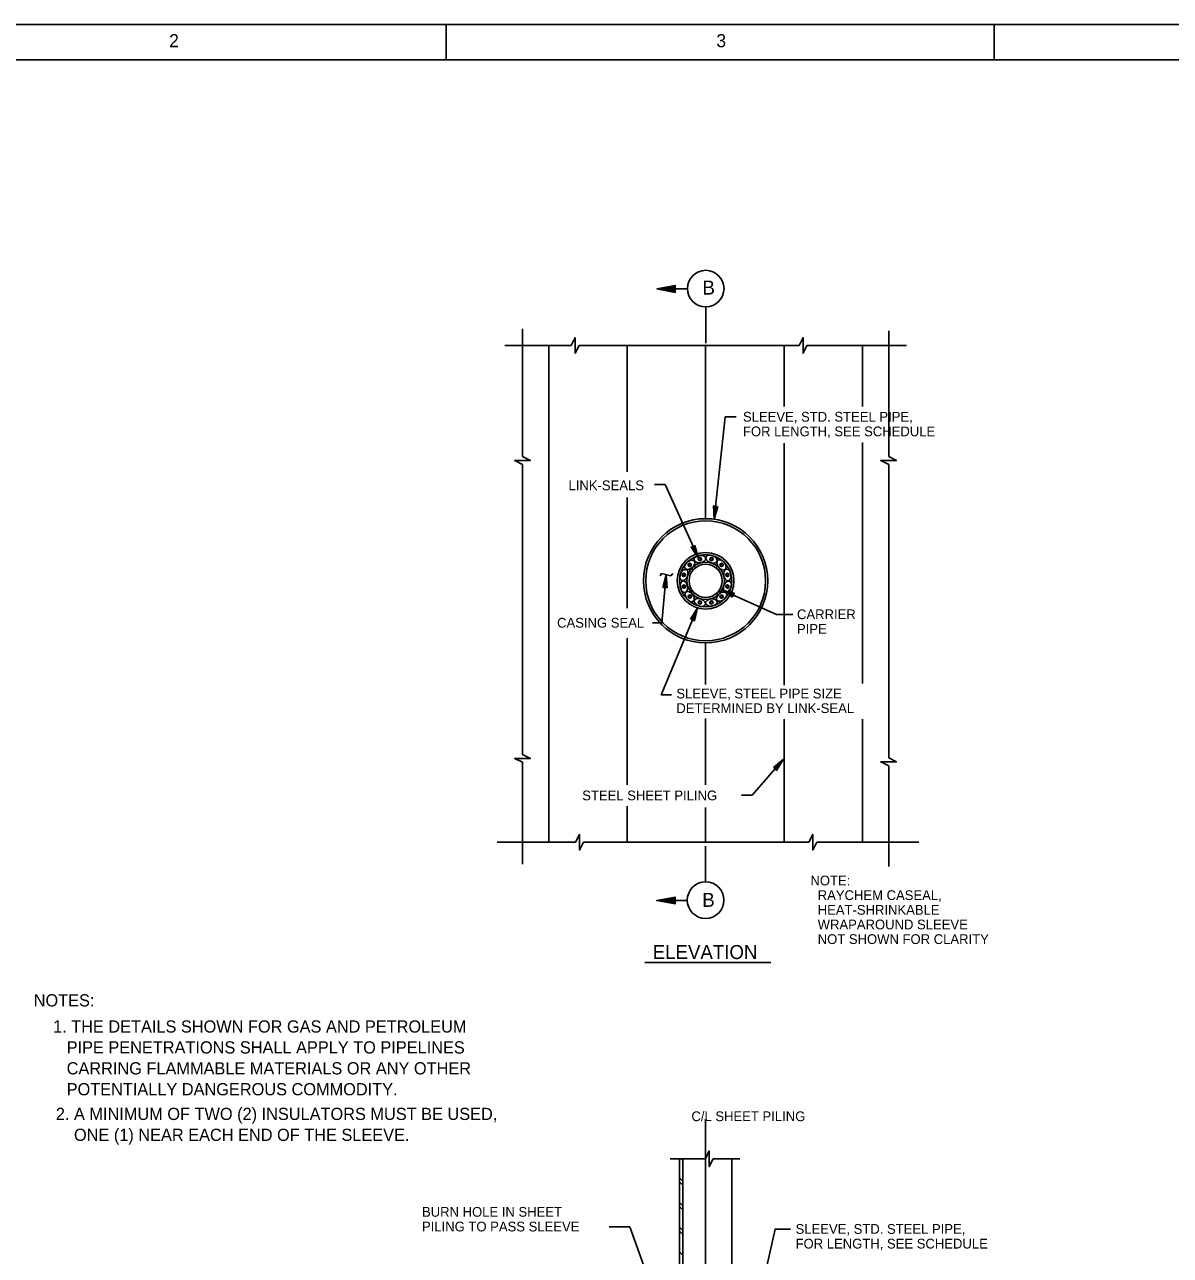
# Model space of a CAD drawing. Extents: x 22422.9 to 22498.9, y 22369.6 to 22415.
# Drawn here: x 22455.11 to 22477.02, y 22391.43 to 22414.97 of the extents above; entities that cross this region are included whole.
import ezdxf

# ---------------------------------------------------------------- set-up
doc = ezdxf.new("R2010")
doc.units = 0
for name, color, linetype in [('Level 1', 7, 'Continuous'), ('Level 10', 7, 'Continuous'), ('Level 2', 7, 'Continuous'), ('Level 3', 7, 'Continuous'), ('Level 4', 7, 'Continuous'), ('Level 7', 7, 'Continuous'), ('Level 8', 7, 'Continuous'), ('Level 9', 7, 'Continuous')]:
    doc.layers.add(name, color=color, linetype=linetype)

msp = doc.modelspace()

# ---------------------------------------------------------------- linework, layer by layer
at = {"layer": 'Level 1'}
for p, q in [((22464.63, 22406.705), (22464.63, 22409.15)), ((22471.63, 22406.705), (22471.63, 22409.109)), ((22464.287, 22408.828), (22465.56, 22408.828)), ((22465.709, 22408.828), (22469.918, 22408.828)), ((22470.067, 22408.828), (22471.973, 22408.828)), ((22464.63, 22401.005), (22464.63, 22406.555)), ((22471.63, 22400.939), (22471.63, 22406.555)), ((22468.216, 22405.596), (22468.216, 22405.596)), ((22468.222, 22405.665), (22468.222, 22405.665)), ((22467.85, 22404.894), (22467.85, 22404.894)), ((22467.864, 22404.826), (22467.864, 22404.826)), ((22467.89, 22404.536), (22467.86, 22404.566)), ((22467.935, 22404.579), (22467.905, 22404.609)), ((22468.327, 22404.577), (22468.357, 22404.607)), ((22468.372, 22404.534), (22468.402, 22404.563)), ((22467.288, 22404.469), (22467.259, 22404.424)), ((22467.288, 22404.469), (22467.466, 22404.424)), ((22467.367, 22404.356), (22467.367, 22404.356)), ((22467.373, 22404.425), (22467.373, 22404.425)), ((22467.466, 22404.424), (22467.502, 22404.469)), ((22467.846, 22404.108), (22467.876, 22404.138)), ((22467.888, 22404.062), (22467.918, 22404.092)), ((22468.367, 22404.059), (22468.338, 22404.088)), ((22468.411, 22404.104), (22468.381, 22404.134)), ((22468.536, 22404.261), (22468.536, 22404.261)), ((22468.603, 22404.243), (22468.603, 22404.243)), ((22467.97, 22403.814), (22467.97, 22403.814)), ((22467.989, 22403.88), (22467.989, 22403.88)), ((22464.63, 22398.906), (22464.63, 22400.856)), ((22469.574, 22400.865), (22469.574, 22400.865)), ((22469.62, 22400.917), (22469.62, 22400.917)), ((22471.63, 22398.863), (22471.63, 22400.789)), ((22464.141, 22399.328), (22465.643, 22399.328)), ((22465.792, 22399.328), (22470.105, 22399.328)), ((22470.254, 22399.328), (22472.207, 22399.328)), ((22468.13, 22384.598), (22468.13, 22394.033)), ((22467.453, 22393.274), (22468.126, 22393.274)), ((22468.275, 22393.274), (22468.785, 22393.274))]:
    msp.add_line(p, q, dxfattribs=at)
msp.add_lwpolyline([(22440.26, 22414.965), (22498.927, 22414.965), (22498.927, 22369.621), (22440.26, 22369.621)], close=True, dxfattribs=at)
for points in [[(22465.56, 22408.828), (22465.634, 22408.978), (22465.634, 22408.679), (22465.709, 22408.828)], [(22469.918, 22408.828), (22469.992, 22408.978), (22469.992, 22408.679), (22470.067, 22408.828)], [(22464.63, 22406.555), (22464.48, 22406.63), (22464.779, 22406.63), (22464.63, 22406.705)], [(22471.63, 22406.555), (22471.48, 22406.63), (22471.779, 22406.63), (22471.63, 22406.705)], [(22464.63, 22400.856), (22464.48, 22400.93), (22464.779, 22400.93), (22464.63, 22401.005)], [(22471.63, 22400.789), (22471.48, 22400.864), (22471.779, 22400.864), (22471.63, 22400.939)], [(22465.643, 22399.328), (22465.717, 22399.478), (22465.717, 22399.179), (22465.792, 22399.328)], [(22470.105, 22399.328), (22470.179, 22399.478), (22470.179, 22399.179), (22470.254, 22399.328)], [(22467.692, 22393.242), (22467.661, 22393.274)], [(22468.126, 22393.274), (22468.2, 22393.424), (22468.2, 22393.124), (22468.275, 22393.274)]]:
    msp.add_lwpolyline(points, dxfattribs=at)
for centre, radius in [((22468.13, 22404.328), 1.188), ((22468.13, 22404.328), 1.146), ((22468.13, 22404.328), 0.542), ((22468.13, 22404.328), 0.5), ((22468.019, 22404.743), 0.0313), ((22468.241, 22404.743), 0.0313), ((22467.826, 22404.632), 0.0313), ((22468.434, 22404.632), 0.0313), ((22467.715, 22404.44), 0.0313), ((22468.545, 22404.44), 0.0313), ((22467.715, 22404.217), 0.0313), ((22467.826, 22404.025), 0.0313), ((22468.434, 22404.025), 0.0313), ((22468.545, 22404.217), 0.0313), ((22468.019, 22403.913), 0.0313), ((22468.241, 22403.913), 0.0313)]:
    msp.add_circle(centre, radius, dxfattribs=at)
for centre, major_axis in [((22468.019, 22404.743), (0.111, 0.015)), ((22468.241, 22404.743), (0.104, -0.043)), ((22468.434, 22404.632), (0.0683, -0.089)), ((22467.715, 22404.44), (0.043, 0.104)), ((22467.826, 22404.632), (0.089, 0.0683)), ((22468.545, 22404.44), (0.015, -0.111)), ((22467.715, 22404.217), (-0.015, 0.111)), ((22468.545, 22404.217), (-0.043, -0.104)), ((22467.826, 22404.025), (-0.0683, 0.089)), ((22468.434, 22404.025), (-0.089, -0.0683)), ((22468.019, 22403.913), (-0.104, 0.043)), ((22468.241, 22403.913), (-0.111, -0.015))]:
    msp.add_ellipse(centre, major_axis=major_axis, ratio=0.623518, dxfattribs=at)
at = {"layer": 'Level 10'}
for p, q in [((22463.167, 22414.293), (22463.167, 22414.965)), ((22473.647, 22414.293), (22473.647, 22414.965)), ((22469.375, 22397.026), (22466.968, 22397.026))]:
    msp.add_line(p, q, dxfattribs=at)
at = {"layer": 'Level 2'}
for p, q in [((22465.13, 22399.328), (22465.13, 22408.828)), ((22466.63, 22406.414), (22466.63, 22408.828)), ((22468.13, 22405.516), (22468.13, 22408.828)), ((22469.63, 22407.662), (22469.63, 22408.828)), ((22471.13, 22407.662), (22471.13, 22408.828)), ((22469.63, 22402.33), (22469.63, 22406.96)), ((22471.13, 22402.363), (22471.13, 22406.971)), ((22466.63, 22403.804), (22466.63, 22405.919)), ((22467.292, 22403.524), (22467.375, 22404.447)), ((22467.977, 22403.809), (22467.282, 22402.145)), ((22467.111, 22403.524), (22467.292, 22403.524)), ((22466.63, 22400.423), (22466.63, 22403.233)), ((22468.13, 22402.347), (22468.13, 22403.141)), ((22467.282, 22402.145), (22467.476, 22402.145)), ((22468.13, 22400.423), (22468.13, 22401.694)), ((22469.63, 22399.328), (22469.63, 22401.681)), ((22471.13, 22399.328), (22471.13, 22401.681)), ((22469.02, 22400.23), (22469.62, 22400.917)), ((22468.817, 22400.23), (22469.02, 22400.23)), ((22466.63, 22399.328), (22466.63, 22400.015)), ((22468.13, 22399.328), (22468.13, 22399.99)), ((22467.63, 22389.342), (22467.63, 22393.274)), ((22467.692, 22389.342), (22467.692, 22393.274)), ((22468.63, 22389.342), (22468.63, 22393.274)), ((22466.283, 22391.97), (22466.68, 22391.97)), ((22467.63, 22389.342), (22466.68, 22391.97))]:
    msp.add_line(p, q, dxfattribs=at)
for points in [[(22468.714, 22407.463), (22468.504, 22407.463), (22468.293, 22405.507)], [(22467.151, 22406.168), (22467.353, 22406.168), (22467.991, 22404.758)], [(22468.361, 22405.751), (22468.293, 22405.507), (22468.279, 22405.76), (22468.349, 22405.752), (22468.301, 22405.576), (22468.291, 22405.748), (22468.336, 22405.743), (22468.308, 22405.643), (22468.303, 22405.736), (22468.322, 22405.734), (22468.315, 22405.712)], [(22467.926, 22405.003), (22467.991, 22404.758), (22467.851, 22404.969), (22467.915, 22404.998), (22467.962, 22404.822), (22467.867, 22404.964), (22467.908, 22404.983), (22467.935, 22404.882), (22467.884, 22404.96), (22467.901, 22404.968), (22467.906, 22404.946)], [(22467.311, 22404.202), (22467.375, 22404.447), (22467.394, 22404.195), (22467.323, 22404.201), (22467.368, 22404.378), (22467.381, 22404.207), (22467.336, 22404.211), (22467.363, 22404.312), (22467.369, 22404.219), (22467.35, 22404.22), (22467.356, 22404.243)], [(22469.796, 22403.681), (22469.483, 22403.681), (22468.432, 22404.154)], [(22468.642, 22404.014), (22468.432, 22404.154), (22468.676, 22404.089), (22468.647, 22404.025), (22468.495, 22404.126), (22468.661, 22404.082), (22468.642, 22404.04), (22468.556, 22404.098), (22468.646, 22404.074), (22468.638, 22404.057), (22468.619, 22404.07)], [(22467.843, 22403.595), (22467.977, 22403.809), (22467.919, 22403.563), (22467.854, 22403.59), (22467.95, 22403.745), (22467.911, 22403.578), (22467.869, 22403.595), (22467.925, 22403.683), (22467.903, 22403.593), (22467.885, 22403.6), (22467.898, 22403.619)], [(22469.425, 22400.756), (22469.62, 22400.917), (22469.487, 22400.702), (22469.434, 22400.748), (22469.574, 22400.865), (22469.484, 22400.719), (22469.45, 22400.749), (22469.53, 22400.814), (22469.481, 22400.736), (22469.467, 22400.748), (22469.485, 22400.762)], [(22469.755, 22391.93), (22469.458, 22391.93), (22468.882, 22389.353)]]:
    msp.add_lwpolyline(points, dxfattribs=at)
for radius in [0.359, 0.318]:
    msp.add_circle((22468.13, 22404.328), radius, dxfattribs=at)
at = {"layer": 'Level 3'}
for p, q in [((22467.548, 22409.909), (22467.781, 22409.909)), ((22468.131, 22408.871), (22468.131, 22409.56)), ((22468.129, 22399.251), (22468.129, 22398.563)), ((22467.546, 22398.213), (22467.779, 22398.213))]:
    msp.add_line(p, q, dxfattribs=at)
for points in [[(22467.548, 22409.958), (22467.548, 22409.976), (22467.198, 22409.909), (22467.548, 22409.844), (22467.548, 22409.958), (22467.287, 22409.91), (22467.531, 22409.864), (22467.531, 22409.939), (22467.375, 22409.91), (22467.515, 22409.884), (22467.515, 22409.919), (22467.465, 22409.91), (22467.498, 22409.904)], [(22467.546, 22398.262), (22467.546, 22398.28), (22467.196, 22398.213), (22467.546, 22398.148), (22467.546, 22398.262), (22467.285, 22398.215), (22467.529, 22398.168), (22467.529, 22398.243), (22467.373, 22398.215), (22467.513, 22398.188), (22467.513, 22398.223), (22467.463, 22398.215), (22467.496, 22398.208)]]:
    msp.add_lwpolyline(points, dxfattribs=at)
for centre in [(22468.131, 22409.916), (22468.129, 22398.22)]:
    msp.add_circle(centre, 0.35, dxfattribs=at)
at = {"layer": 'Level 8'}
for p, q in [((22468.293, 22405.507), (22468.293, 22405.507)), ((22468.301, 22405.576), (22468.301, 22405.576)), ((22467.962, 22404.822), (22467.962, 22404.822)), ((22467.991, 22404.758), (22467.991, 22404.758)), ((22468.012, 22404.769), (22467.992, 22404.75)), ((22467.999, 22404.724), (22467.992, 22404.75)), ((22468.012, 22404.769), (22468.038, 22404.762)), ((22468.045, 22404.736), (22468.038, 22404.762)), ((22468.215, 22404.737), (22468.222, 22404.762)), ((22468.248, 22404.769), (22468.222, 22404.762)), ((22468.248, 22404.769), (22468.267, 22404.75)), ((22468.26, 22404.724), (22468.267, 22404.75)), ((22467.807, 22404.651), (22467.8, 22404.625)), ((22467.819, 22404.606), (22467.8, 22404.625)), ((22467.807, 22404.651), (22467.833, 22404.658)), ((22467.845, 22404.613), (22467.819, 22404.606)), ((22467.852, 22404.639), (22467.833, 22404.658)), ((22467.845, 22404.613), (22467.852, 22404.639)), ((22468.026, 22404.717), (22467.999, 22404.724)), ((22468.026, 22404.717), (22468.045, 22404.736)), ((22468.234, 22404.717), (22468.215, 22404.737)), ((22468.234, 22404.717), (22468.26, 22404.724)), ((22468.408, 22404.639), (22468.427, 22404.658)), ((22468.415, 22404.613), (22468.408, 22404.639)), ((22468.415, 22404.613), (22468.441, 22404.606)), ((22468.453, 22404.651), (22468.427, 22404.658)), ((22468.441, 22404.606), (22468.46, 22404.625)), ((22468.453, 22404.651), (22468.46, 22404.625)), ((22467.368, 22404.378), (22467.368, 22404.378)), ((22467.375, 22404.447), (22467.375, 22404.447)), ((22467.689, 22404.447), (22467.708, 22404.466)), ((22467.689, 22404.447), (22467.696, 22404.42)), ((22467.722, 22404.413), (22467.696, 22404.42)), ((22467.734, 22404.459), (22467.708, 22404.466)), ((22467.741, 22404.433), (22467.722, 22404.413)), ((22467.741, 22404.433), (22467.734, 22404.459)), ((22468.519, 22404.433), (22468.526, 22404.459)), ((22468.519, 22404.433), (22468.538, 22404.414)), ((22468.526, 22404.459), (22468.552, 22404.466)), ((22468.538, 22404.414), (22468.564, 22404.421)), ((22468.571, 22404.447), (22468.552, 22404.466)), ((22468.571, 22404.447), (22468.564, 22404.421)), ((22467.689, 22404.21), (22467.696, 22404.236)), ((22467.689, 22404.21), (22467.708, 22404.191)), ((22467.722, 22404.243), (22467.696, 22404.236)), ((22467.734, 22404.198), (22467.708, 22404.191)), ((22467.741, 22404.224), (22467.722, 22404.243)), ((22467.741, 22404.224), (22467.734, 22404.198)), ((22467.819, 22404.051), (22467.8, 22404.032)), ((22467.845, 22404.044), (22467.819, 22404.051)), ((22467.845, 22404.044), (22467.852, 22404.017)), ((22468.415, 22404.044), (22468.408, 22404.018)), ((22468.415, 22404.044), (22468.441, 22404.051)), ((22468.432, 22404.154), (22468.432, 22404.154)), ((22468.441, 22404.051), (22468.46, 22404.032)), ((22468.495, 22404.126), (22468.495, 22404.126)), ((22468.519, 22404.224), (22468.538, 22404.243)), ((22468.519, 22404.224), (22468.526, 22404.198)), ((22468.526, 22404.198), (22468.552, 22404.191)), ((22468.538, 22404.243), (22468.564, 22404.236)), ((22468.571, 22404.21), (22468.552, 22404.191)), ((22468.571, 22404.21), (22468.564, 22404.236)), ((22467.807, 22404.005), (22467.8, 22404.032)), ((22467.807, 22404.005), (22467.833, 22403.998)), ((22467.852, 22404.017), (22467.833, 22403.998)), ((22467.977, 22403.809), (22467.977, 22403.809)), ((22468, 22403.932), (22467.993, 22403.906)), ((22468.012, 22403.887), (22467.993, 22403.906)), ((22468.026, 22403.939), (22468, 22403.932)), ((22468.012, 22403.887), (22468.038, 22403.894)), ((22468.026, 22403.939), (22468.045, 22403.92)), ((22468.045, 22403.92), (22468.038, 22403.894)), ((22468.234, 22403.939), (22468.215, 22403.92)), ((22468.215, 22403.92), (22468.222, 22403.894)), ((22468.248, 22403.887), (22468.222, 22403.894)), ((22468.234, 22403.939), (22468.26, 22403.932)), ((22468.248, 22403.887), (22468.267, 22403.906)), ((22468.26, 22403.932), (22468.267, 22403.906)), ((22468.408, 22404.018), (22468.427, 22403.999)), ((22468.453, 22404.006), (22468.427, 22403.999)), ((22468.453, 22404.006), (22468.46, 22404.032)), ((22467.95, 22403.745), (22467.95, 22403.745))]:
    msp.add_line(p, q, dxfattribs=at)
for points in [[(22467.692, 22392.846), (22467.63, 22392.909)], [(22467.692, 22392.771), (22467.63, 22392.833)], [(22467.692, 22392.375), (22467.63, 22392.437)], [(22467.692, 22392.3), (22467.63, 22392.362)], [(22467.692, 22391.904), (22467.63, 22391.966)], [(22467.692, 22391.828), (22467.63, 22391.891)], [(22467.692, 22391.432), (22467.63, 22391.495)]]:
    msp.add_lwpolyline(points, dxfattribs=at)
for centre in [(22468.019, 22404.743), (22468.241, 22404.743), (22467.826, 22404.632), (22468.434, 22404.632), (22467.715, 22404.44), (22468.545, 22404.44), (22467.715, 22404.217), (22467.826, 22404.025), (22468.434, 22404.025), (22468.545, 22404.217), (22468.019, 22403.913), (22468.241, 22403.913)]:
    msp.add_circle(centre, 0.0233, dxfattribs=at)
at = {"layer": 'Level 9'}
msp.add_line((22442.26, 22414.293), (22494.591, 22414.293), dxfattribs=at)

# ---------------------------------------------------------------- texts
at = {"layer": 'Level 1'}
for s, p in [('2', (22457.871, 22414.533)), ('3', (22468.335, 22414.533))]:
    msp.add_text(s, height=0.25, dxfattribs=at).set_placement(p)
at = {"layer": 'Level 3'}
for s, height, p in [('B', 0.267, (22468.07, 22409.802)), ('B', 0.267, (22468.066, 22398.092)), ('ELEVATION', 0.2667, (22467.118, 22397.094))]:
    msp.add_text(s, height=height, dxfattribs=at).set_placement(p)
at = {"layer": 'Level 4'}
for s, height, p in [('SLEEVE, STD. STEEL PIPE,', 0.18667, (22468.844, 22407.372)), ('FOR LENGTH, SEE SCHEDULE', 0.18667, (22468.844, 22407.092)), ('LINK-SEALS', 0.1867, (22465.508, 22406.06)), ('CASING SEAL', 0.18667, (22465.289, 22403.432)), ('CARRIER', 0.1867, (22469.877, 22403.594)), ('PIPE', 0.1867, (22469.877, 22403.314)), ('SLEEVE, STEEL PIPE SIZE', 0.18667, (22467.57, 22402.078)), ('DETERMINED BY LINK-SEAL', 0.18667, (22467.57, 22401.798)), ('STEEL SHEET PILING', 0.18667, (22465.77, 22400.129)), ('NOTE:', 0.1867, (22470.134, 22398.502)), ('  RAYCHEM CASEAL,', 0.18667, (22470.134, 22398.222)), ('  HEAT-SHRINKABLE', 0.18667, (22470.134, 22397.941)), ('  WRAPAROUND SLEEVE', 0.18667, (22470.134, 22397.661)), ('  NOT SHOWN FOR CLARITY', 0.18667, (22470.134, 22397.381)), ('C/L SHEET PILING', 0.18667, (22467.858, 22393.993)), ('BURN HOLE IN SHEET', 0.18667, (22462.706, 22392.165)), ('PILING TO PASS SLEEVE', 0.18667, (22462.706, 22391.884)), ('SLEEVE, STD. STEEL PIPE,', 0.18667, (22469.85, 22391.838)), ('FOR LENGTH, SEE SCHEDULE', 0.18667, (22469.85, 22391.557))]:
    msp.add_text(s, height=height, dxfattribs=at).set_placement(p)
at = {"layer": 'Level 7'}
for s, height, p in [('NOTES:', 0.2333, (22455.281, 22396.187)), ('1. THE DETAILS SHOWN FOR GAS AND PETROLEUM', 0.23333, (22455.651, 22395.687)), ('   PIPE PENETRATIONS SHALL APPLY TO PIPELINES', 0.23333, (22455.651, 22395.287)), ('   CARRING FLAMMABLE MATERIALS OR ANY OTHER', 0.23333, (22455.651, 22394.887)), ('   POTENTIALLY DANGEROUS COMMODITY.', 0.23333, (22455.651, 22394.487)), ('2. A MINIMUM OF TWO (2) INSULATORS MUST BE USED,', 0.23333, (22455.704, 22394.015)), ('    ONE (1) NEAR EACH END OF THE SLEEVE.', 0.23333, (22455.704, 22393.615))]:
    msp.add_text(s, height=height, dxfattribs=at).set_placement(p)

doc.saveas('drawing.dxf')
